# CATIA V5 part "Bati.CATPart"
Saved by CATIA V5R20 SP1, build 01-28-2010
Part number: Bati
Bounding box of the stored display mesh (mm): x -10 to 10, y -40 to 40, z 0 to 37
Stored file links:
  E:\EDELI\gcausse\Edeli_2012_679_gcausse\Bati.CATPart
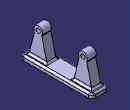
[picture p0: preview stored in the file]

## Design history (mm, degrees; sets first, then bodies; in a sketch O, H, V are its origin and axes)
Body1 (main body)
  Sketch1 on xy-plane, origin (0, 0, 0), H (1, 0, 0), V (0, 1, 0)
    line L1 (-10, -40) -> (10, -40)
    line L2 (10, -40) -> (10, 40)
    line L3 (10, 40) -> (-10, 40)
    line L4 (-10, 40) -> (-10, -40)
    horizontal: L1 H, L3 H
    vertical: L2 V, L4 V
  Pad1: profile Sketch1, direction (0, 0, 1), length 5
  Sketch2 on end face of Pad1, origin (0, 0, 5), H (1, 0, 0), V (0, 1, 0)
    line L1 (-5, 35) -> (5, 35)
    line L2 (5, 35) -> (5, 15)
    line L3 (5, 15) -> (-5, 15)
    line L4 (-5, 15) -> (-5, 35)
    line L5 (-5, -35) -> (5, -35)
    line L6 (5, -35) -> (5, -15)
    line L7 (5, -15) -> (-5, -15)
    line L8 (-5, -15) -> (-5, -35)
    reference projected line E1 (-10, 40) -> (-10, -40) from edge [face of Pad1 from Sketch1.L4 | end face of Pad1]
    reference projected line E2 (-10, 40) -> (-10, -40) from edge [face of Pad1 from Sketch1.L4 | end face of Pad1]
    reference projected line E3 (-10, -40) -> (10, -40) from edge [face of Pad1 from Sketch1.L1 | end face of Pad1]
    reference projected line E4 (-10, -40) -> (10, -40) from edge [face of Pad1 from Sketch1.L1 | end face of Pad1]
    reference projected line E5 (-10, -40) -> (10, -40) from edge [face of Pad1 from Sketch1.L1 | end face of Pad1]
    reference projected line E6 (-10, -40) -> (10, -40) from edge [face of Pad1 from Sketch1.L1 | end face of Pad1]
    distance L4 E1 = 5
    distance L8 E2 = 5
    distance L5 E3 = 5
    distance L7 E4 = 25
    distance L3 E5 = 55
    distance L1 E6 = 75
    distance L4 L2 = 10
    horizontal: L1 H, L3 H, L5 H, L7 H
    vertical: L2 V, L4 V, L6 V, L8 V
  Pad2: profile Sketch2, direction (0, 0, 1), length 35
  Sketch3 on face of Pad2 from Sketch2.L6, origin (5, 0, 0), H (0, 1, 0), V (0, 0, 1)
    line L1 (-35, 5) -> (-29.0677, 29.286)
    point P1 (-35, 5)
    line L2 (-20.9323, 29.286) -> (-15, 5)
    point P4 (-15, 5)
    arc A1 centre (-25, 32) radius 4.89 from (-20.9323, 29.286) to (-29.0677, 29.286) ccw
    point P5 (-25, 32)
    point P6 (-55, 40)
    reference projected point E1 (-15, 5) from vertex [face of Pad2 from Sketch2.L7 | end face of Pad1 | face of Pad2 from Sketch2.L6]
    reference projected point E2 (-35, 5) from vertex [face of Pad2 from Sketch2.L6 | end face of Pad1 | face of Pad2 from Sketch2.L5]
    reference projected line E3 (-15, 5) -> (-15, 40) from edge [face of Pad2 from Sketch2.L7 | face of Pad2 from Sketch2.L6]
    reference projected line E4 (-35, 5) -> (-35, 40) from edge [face of Pad2 from Sketch2.L6 | face of Pad2 from Sketch2.L5]
    reference projected line E5 (-35, 40) -> (-15, 40) from edge [face of Pad2 from Sketch2.L6 | end face of Pad2]
    line L3 (-15, 5) -> (-15, 50)
    line L4 (-15, 50) -> (-35, 50)
    line L5 (-35, 50) -> (-35, 5)
    distance P5 E5 = 8
    length L2 = 25
    length L1 = 25
    coincidence: P4 E1, P1 E2
    equidistance: E3 E4 P5
    vertical: L3 V, L5 V
    horizontal: L4 H
  Pocket1: profile Sketch3, direction (-1, 0, 0), length 35
  Sketch4 on face of Pad2 from Sketch2.L6, origin (5, -25.3906, 32.2803), H (0, 1, 0), V (0, 0, 1)
    point P1 (0.3906, -0.2803)
    reference projected arc E1 centre (0.3906, -0.2803) radius 4.89 from (4.4582, -2.9943) to (-3.6771, -2.9943) ccw from edge [face of Pad2 from Sketch2.L6 | face of Pocket1 from Sketch3.A1]
    concentricity: P1 E1
  Hole1: placed by Sketch4, at (5, -25, 32) direction (-1, 0, 0), diameter 5, depth 10
  Sketch5 on face of Pad2 from Sketch2.L2, origin (5, 0, 0), H (0, 1, 0), V (0, 0, 1)
    line L1 (15, 5) -> (20.7767, 29.3234)
    point P1 (15, 5)
    arc A1 centre (25, 32) radius 5 from (20.7767, 29.3234) to (29.2233, 29.3234) cw
    point P3 (25, 32)
    line L2 (29.2233, 29.3234) -> (35, 5)
    point P5 (35, 5)
    reference projected point E1 (15, 5) from vertex [face of Pad2 from Sketch2.L2 | end face of Pad1 | face of Pad2 from Sketch2.L3]
    reference projected point E2 (35, 5) from vertex [face of Pad2 from Sketch2.L2 | end face of Pad1 | face of Pad2 from Sketch2.L1]
    reference projected line E3 (15, 40) -> (35, 40) from edge [face of Pad2 from Sketch2.L2 | end face of Pad2]
    reference projected line E4 (35, 5) -> (35, 40) from edge [face of Pad2 from Sketch2.L1 | face of Pad2 from Sketch2.L2]
    reference projected line E5 (15, 5) -> (15, 40) from edge [face of Pad2 from Sketch2.L2 | face of Pad2 from Sketch2.L3]
    line L3 (35, 5) -> (35, 50)
    line L4 (35, 50) -> (15, 50)
    line L5 (15, 50) -> (15, 5)
    radius A1 = 5
    distance P3 E3 = 8
    length L2 = 25
    length L1 = 25
    coincidence: P1 E1, P5 E2
    equidistance: E4 E5 P3
    vertical: L3 V, L5 V
    horizontal: L4 H
  Pocket2: profile Sketch5, direction (-1, 0, 0), length 35
  Sketch6 on face of Pad2 from Sketch2.L2, origin (5, 26.0729, 32.6317), H (0, 1, 0), V (0, 0, 1)
    point P1 (-1.0729, -0.6317)
    reference projected arc E1 centre (-1.0729, -0.6317) radius 5 from (3.1504, -3.3083) to (-5.2962, -3.3083) ccw from edge [face of Pocket2 from Sketch5.A1 | face of Pad2 from Sketch2.L2]
    concentricity: P1 E1
  Hole2: placed by Sketch6, at (5, 25, 32) direction (-1, 0, 0), diameter 5, depth 10
  Fillet1: radius 2, on end face of Pad1
  Fillet2: radius 4, on edge [face of Pad1 from Sketch1.L4 | face of Pad1 from Sketch1.L3]; edge [face of Pad1 from Sketch1.L3 | face of Pad1 from Sketch1.L2]; edge [face of Pad1 from Sketch1.L1 | face of Pad1 from Sketch1.L4]; edge [face of Pad1 from Sketch1.L2 | face of Pad1 from Sketch1.L1]
  Fillet3: radius 1, on edge [face of Pocket2 from Sketch5.L2 | face of Pocket2 from Sketch5.A1]; edge [face of Pocket2 from Sketch5.A1 | face of Pocket2 from Sketch5.L1]; edge [face of Pocket1 from Sketch3.L2 | face of Pocket1 from Sketch3.A1]; edge [face of Pocket1 from Sketch3.A1 | face of Pocket1 from Sketch3.L1]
